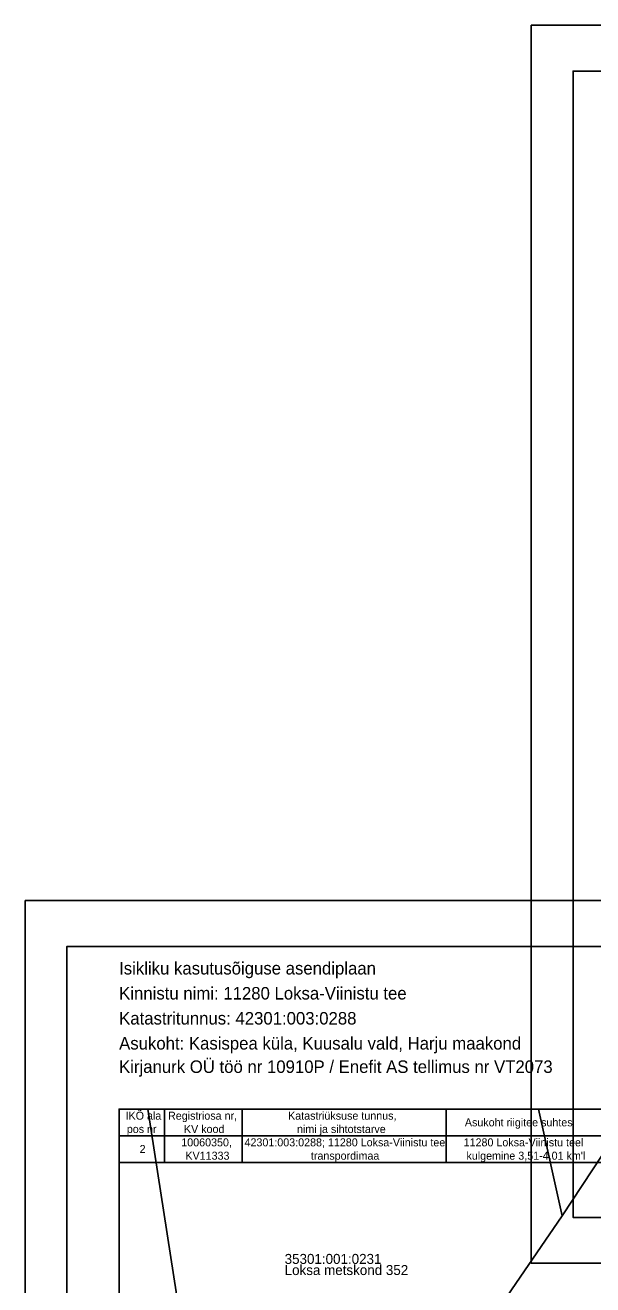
# Model space of a CAD drawing. Extents: x 599446 to 599962, y 6608194 to 6608886.
# Drawn here: x 599713.8 to 599815.8, y 6608659.5 to 6608886.1 of the extents above; entities that cross this region are included whole.
import ezdxf

# ---------------------------------------------------------------- set-up
doc = ezdxf.new("R2010")
doc.units = 0
for name, color, linetype in [('PIIR', 7, 'Continuous'), ('VORMISTUS_2', 7, 'Continuous'), ('VORMISTUS_3', 7, 'Continuous')]:
    doc.layers.add(name, color=color, linetype=linetype)

msp = doc.modelspace()

# ---------------------------------------------------------------- linework, layer by layer
at = {"layer": 'PIIR'}
for points in [[(599735.83, 6608691.11), (599752.04, 6608586.7), (599730.69, 6608596.81)], [(599730.69, 6608555.17), (599752.04, 6608586.7), (599810.31, 6608671.87), (599822.96, 6608691.11)], [(599806.09, 6608691.11), (599810.31, 6608671.87), (599752.04, 6608586.7), (599735.83, 6608691.11)], [(599822.96, 6608691.11), (599810.31, 6608671.87), (599806.09, 6608691.11)]]:
    msp.add_lwpolyline(points, dxfattribs=at)
at = {"layer": 'VORMISTUS_2'}
for p, q in [((599738.85, 6608691.11), (599738.85, 6608681.51)), ((599752.83, 6608691.11), (599752.83, 6608681.51)), ((599789.49, 6608691.11), (599789.49, 6608681.51)), ((599730.69, 6608686.31), (599829.69, 6608686.31))]:
    msp.add_line(p, q, dxfattribs=at)
for points in [[(599713.81, 6608728.61), (599871.31, 6608728.61), (599871.31, 6608505.86), (599713.81, 6608505.86)], [(599721.31, 6608514.11), (599863.81, 6608514.11), (599863.81, 6608720.36), (599721.31, 6608720.36)], [(599721.31, 6608720.36), (599863.81, 6608720.36), (599863.81, 6608514.11), (599721.31, 6608514.11)], [(599854.44, 6608533.61), (599730.69, 6608533.61), (599730.69, 6608691.11), (599854.44, 6608691.11)], [(599730.69, 6608691.11), (599829.69, 6608691.11), (599829.69, 6608681.51), (599730.69, 6608681.51)]]:
    msp.add_lwpolyline(points, close=True, dxfattribs=at)
at = {"layer": 'VORMISTUS_3'}
for points in [[(599804.77, 6608886.11), (599962.27, 6608886.11), (599962.27, 6608663.36), (599804.77, 6608663.36)], [(599812.27, 6608671.61), (599954.77, 6608671.61), (599954.77, 6608877.86), (599812.27, 6608877.86)], [(599812.27, 6608877.86), (599954.77, 6608877.86), (599954.77, 6608671.61), (599812.27, 6608671.61)]]:
    msp.add_lwpolyline(points, close=True, dxfattribs=at)

# ---------------------------------------------------------------- texts
at = {"layer": 'PIIR'}
for s, p in [('35301:001:0231', (599760.44, 6608663.24)), ('Loksa metskond 352', (599760.44, 6608661.24))]:
    msp.add_text(s, height=1.8, dxfattribs=at).set_placement(p)
at = {"layer": 'VORMISTUS_2'}
for s, height, p in [('Isikliku kasutusõiguse asendiplaan', 2.25, (599730.69, 6608715.31)), ('Kinnistu nimi: 11280 Loksa-Viinistu tee', 2.25, (599730.69, 6608710.81)), ('Katastritunnus: 42301:003:0288', 2.25, (599730.69, 6608706.31)), ('Asukoht: Kasispea küla, Kuusalu vald, Harju maakond', 2.25, (599730.69, 6608701.81)), ('IKÕ ala', 1.44, (599731.85, 6608689.19)), ('Registriosa nr,', 1.44, (599739.48, 6608689.19)), ('Katastriüksuse tunnus,', 1.44, (599761.06, 6608689.19)), ('KV kood', 1.44, (599742.34, 6608686.79)), ('nimi ja sihtotstarve', 1.44, (599762.66, 6608686.79)), ('Asukoht riigitee suhtes ', 1.44, (599792.83, 6608687.99)), ('pos nr', 1.44, (599732.07, 6608686.79)), ('2', 1.44, (599734.37, 6608683.19)), ('10060350,', 1.44, (599741.86, 6608684.39)), ('42301:003:0288; 11280 Loksa-Viinistu tee', 1.44, (599753.23, 6608684.39)), ('11280 Loksa-Viinistu teel', 1.44, (599792.61, 6608684.39)), ('KV11333', 1.44, (599742.6, 6608681.99)), ('transpordimaa', 1.44, (599765.15, 6608681.99)), ("kulgemine 3,51-4,01 km'l", 1.44, (599793.12, 6608681.99))]:
    msp.add_text(s, height=height, dxfattribs=at).set_placement(p)
msp.add_text('Kirjanurk OÜ töö nr 10910P / Enefit AS tellimus nr VT2073', height=2.25, rotation=360, dxfattribs=at).set_placement((599730.68, 6608697.6))

doc.saveas('drawing.dxf')
